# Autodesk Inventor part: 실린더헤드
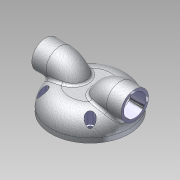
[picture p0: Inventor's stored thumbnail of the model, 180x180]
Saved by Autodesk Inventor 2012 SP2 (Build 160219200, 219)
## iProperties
Manager: KYOUNG IL JANG
Company: 한국ATC센터
Created: 2012-10
Part Number: 실린더헤드
Document SubType Name: Modeling
Density: 1 g/cm^3
Checked By: KYOUNG IL JANG
Vendor: CBT Solutions
Designer: KYOUNG IL JANG
Material: 기본값
Author: KYOUNG IL JANG
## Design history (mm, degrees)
sketch "스케치1"
  geometry: C1 r 42.5 at (0, 0); 1 further point
  constraints: 1 centre point, 1 coincident
  dimensions: "d0" = 85 diameter of C1
extrude "돌출1" new body sketch "스케치1" distance "d1" = 25; taper "d2" = 0 deg
fillet "모깎기1" dims "d3" = 20
sketch "스케치2"
  geometry: C1 r 30 at (0, 0); 1 further point
  constraints: 1 centre point, 1 coincident
  dimensions: "d4" = 60 diameter of C1
extrude "돌출2" join sketch "스케치2" distance "d5" = 5; taper "d6" = 0 deg
sketch "스케치3"
  geometry: L1 (-42.5, 0)-(42.5, 0) reference; L2 (-48.5, 30)-(-33, 30); L3 (-17.545, 18.141)-(-12.684, 0); A1 r 16 centre (-33, 14) between (-17.545, 18.141) and (-33, 30); 1 further point
  constraints: 4 end point, 2 point on circle, 2 tangent, 1 centre point, 1 parallel, 1 point on line
  dimensions: "d7" = 16 radius of A1; "d8" = 6 horizontal distance of L2.start L1.start; "d9" = 30 distance between parallel lines of L2 L1; "d11" = 105 deg angle of L3 L1; "d36" = 15.5 distance of L2.start L2.end
node "작업 평면1"
sketch "스케치4"
  geometry: C1 r 15 at (0, 0); C2 r 12 at (0, 0); 2 further points
  constraints: 2 centre point, 2 coincident
  dimensions: "d12" = 30 diameter of C1; "d13" = 3 radial gap between concentric circles of C2 C1
feature "스윕1" dims "d14" = 0
feature "스윕2" dims "d15" = 0
sketch "스케치5"
  geometry: L1 (30, -5)-(-30, -5) reference; L2 (0, -5)-(0, 10); L3 (0, 10)-(-10, 10); A1 r 15 centre (-10, -5) between (-10, 10) and (-25, -5); 1 further point
  constraints: 4 end point, 2 perpendicular, 2 point on circle, 1 centre point, 1 midpoint, 1 point on line, 1 tangent
  dimensions: "d16" = 15 distance of L2.start L2.end; "d17" = 15 radius of A1; "d18" = 5 distance of L1.end A1.end
revolve "회전1" sketch "스케치5" stored, may be unused: angle "d19" = 90 deg
fillet "모깎기2" dims "d20" = 3
node "작업 평면2"
sketch "스케치6"
  geometry: L1 (0, 0)-(36.25, 0); C1 r 4.75 at (25.633, 25.633); C2 r 2.75 at (25.633, 25.633); A1 r 36.25 centre (0, 0) between (25.633, 25.633) and (36.25, 0); 1 further point
  constraints: 3 centre point, 2 coincident, 2 end point, 2 point on circle, 1 horizontal
  dimensions: "d22" = 72.5 diameter of A1; "d23" = 5.5 diameter of C2; "d24" = 9.5 diameter of C1; "d37" = 45 deg dimension on point (0, 0) C1.centre L1.end
extrude "돌출3" cut sketch "스케치6" stored distance "d25" = 5; taper "d26" = 0 deg
extrude "돌출4" cut sketch "스케치6" stored distance "d27" = 5; taper "d28" = 0 deg
chamfer "모따기1" distance "d33" = 1; stored, may be unused: second distance "d34" = 2, angle "d35" = 45 deg
node "솔리드1"
mirror "대칭1"
pattern_circular "원형 패턴1" dims angle "d30" = 360 deg
